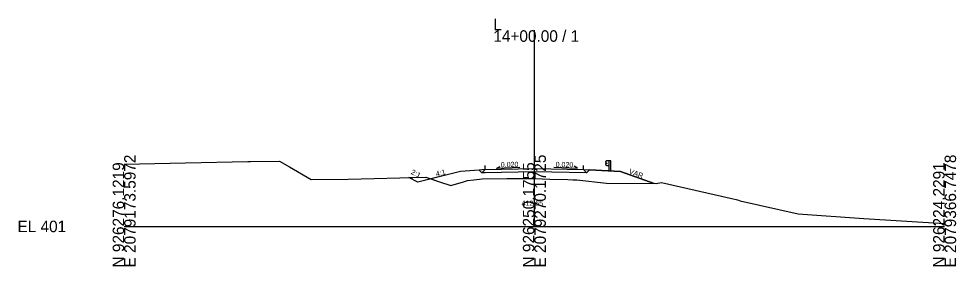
# Model space of a CAD drawing. Extents: x -26 to 10503, y -10 to 9546.
# Drawn here: x -25.7 to 202.8, y 7990.3 to 8050.5 of the extents above; entities that cross this region are included whole.
import ezdxf

# ---------------------------------------------------------------- set-up
doc = ezdxf.new("R2010")
doc.units = 0
for name, color, linetype in [('Default', 7, 'Continuous'), ('Exist XS Center Line Elevation Label', 7, 'Continuous'), ('Exist XS Ground Line', 7, 'Continuous'), ('Old_Level_3', 7, 'Continuous'), ('Old_Level_58', 7, 'Continuous'), ('Old_Level_63', 7, 'Continuous'), ('Old_Level_8', 7, 'Continuous'), ('Prop XS Ditch Slope Text', 7, 'Continuous'), ('Prop XS EOT Tick Mark', 7, 'Continuous'), ('Prop XS Finish Grade', 7, 'Continuous'), ('Prop XS Finish Grade Earthwork', 7, 'Continuous'), ('Prop XS Finish Grade Pavement', 7, 'Continuous'), ('Prop XS Pvmt Edge Slope', 7, 'Continuous'), ('Prop XS SE Text', 7, 'Continuous'), ('Prop XS Side Slope Text', 7, 'Continuous'), ('Prop XS Subgrade Earthwork', 7, 'Continuous')]:
    doc.layers.add(name, color=color, linetype=linetype)

msp = doc.modelspace()

# ---------------------------------------------------------------- linework, layer by layer
at = {"layer": 'Default'}
for points in [[(100, 8013.32), (88, 8013.08), (87.23, 8013.07), (86.58, 8013.72), (81.99, 8013.35), (74.8, 8011.55), (76.87, 8010.82), (79.61, 8009.92), (82.69, 8010.82), (83.66, 8011.16), (85.22, 8011.36), (87.25, 8011.62), (93.27, 8011.68), (98.23, 8011.7), (100, 8011.65), (103.79, 8011.54), (108.18, 8011.39), (109.4, 8011.34), (110.32, 8011.3), (117.57, 8010.5), (129.18, 8010.41), (121, 8013.38), (113.43, 8013.76), (112.74, 8013.07)], [(69.38, 8011.88), (73.58, 8011.99), (74.8, 8011.55), (71.63, 8010.76)]]:
    msp.add_lwpolyline(points, close=True, dxfattribs=at)
at = {"layer": 'Exist XS Ground Line'}
for p, q in [((0, 8015.12), (14.95, 8015.48)), ((14.95, 8015.48), (30.18, 8015.79)), ((30.18, 8015.79), (30.81, 8015.82)), ((30.81, 8015.82), (37.91, 8015.92)), ((37.91, 8015.92), (40.31, 8014.54)), ((40.31, 8014.54), (45.6, 8011.43)), ((45.6, 8011.43), (54.62, 8011.52)), ((54.62, 8011.52), (73.58, 8011.99)), ((73.58, 8011.99), (76.87, 8010.82)), ((76.87, 8010.82), (79.61, 8009.92)), ((79.61, 8009.92), (82.69, 8010.82)), ((82.69, 8010.82), (83.66, 8011.16)), ((83.66, 8011.16), (85.22, 8011.36)), ((85.22, 8011.36), (87.25, 8011.62)), ((87.25, 8011.62), (93.27, 8011.68)), ((93.27, 8011.68), (98.23, 8011.7)), ((98.23, 8011.7), (100, 8011.65)), ((100, 8011.65), (103.79, 8011.54)), ((103.79, 8011.54), (108.18, 8011.39)), ((108.18, 8011.39), (109.4, 8011.34)), ((109.4, 8011.34), (110.32, 8011.3)), ((110.32, 8011.3), (117.57, 8010.5)), ((117.57, 8010.5), (129.66, 8010.41)), ((129.66, 8010.41), (131, 8010.67)), ((131, 8010.67), (148.44, 8006.75)), ((148.44, 8006.75), (149.16, 8006.52)), ((149.16, 8006.52), (149.76, 8006.35)), ((149.76, 8006.35), (150.18, 8006.25)), ((150.18, 8006.25), (164.34, 8003.08)), ((164.34, 8003.08), (180.34, 8001.89)), ((180.34, 8001.89), (200, 8000.69))]:
    msp.add_line(p, q, dxfattribs=at)
at = {"layer": 'Old_Level_3'}
for p, q in [((117.35, 8015.73), (117.32, 8015.67)), ((117.32, 8015.67), (117.35, 8015.61)), ((117.35, 8015.11), (117.32, 8015.05)), ((117.32, 8015.05), (117.35, 8014.99)), ((117.64, 8015.93), (117.35, 8015.73)), ((117.35, 8015.61), (117.64, 8015.41)), ((117.64, 8015.31), (117.35, 8015.11)), ((117.35, 8014.99), (117.64, 8014.79)), ((118.14, 8015.93), (117.64, 8015.93)), ((117.64, 8015.41), (117.64, 8015.31)), ((117.64, 8014.79), (118.14, 8014.79)), ((118.64, 8015.93), (118.14, 8015.93)), ((118.14, 8015.93), (118.14, 8013.53)), ((118.64, 8013.5), (118.64, 8015.93))]:
    msp.add_line(p, q, dxfattribs=at)
at = {"layer": 'Old_Level_63'}
for p, q in [((100, 8000), (100, 8047.75)), ((0, 8000), (100, 8000)), ((100, 8000), (200, 8000))]:
    msp.add_line(p, q, dxfattribs=at)
at = {"layer": 'Old_Level_8'}
msp.add_line((112, 8013.83), (112.74, 8013.07), dxfattribs=at)
at = {"layer": 'Prop XS EOT Tick Mark'}
for p, q in [((88, 8013.83), (88, 8014.83)), ((112, 8013.83), (112, 8014.83))]:
    msp.add_line(p, q, dxfattribs=at)
at = {"layer": 'Prop XS Finish Grade'}
for p, q in [((88, 8013.83), (86.58, 8013.72)), ((112, 8013.83), (113.43, 8013.76))]:
    msp.add_line(p, q, dxfattribs=at)
at = {"layer": 'Prop XS Finish Grade Earthwork'}
for p, q in [((81.99, 8013.35), (71.63, 8010.76)), ((86.58, 8013.72), (81.99, 8013.35)), ((113.43, 8013.76), (121, 8013.38)), ((121, 8013.38), (129.18, 8010.41)), ((71.63, 8010.76), (69.38, 8011.88))]:
    msp.add_line(p, q, dxfattribs=at)
at = {"layer": 'Prop XS Finish Grade Pavement'}
for p, q in [((88, 8013.83), (100, 8014.07)), ((100, 8014.07), (112, 8013.83))]:
    msp.add_line(p, q, dxfattribs=at)
at = {"layer": 'Prop XS Pvmt Edge Slope'}
msp.add_line((88, 8013.83), (87.23, 8013.07), dxfattribs=at)
at = {"layer": 'Prop XS SE Text'}
for points in [[(104.77, 8014.46), (110.52, 8014.18), (109.67, 8014.65)], [(96.49, 8014.38), (90.73, 8014.1), (91.58, 8014.57)]]:
    msp.add_lwpolyline(points, dxfattribs=at)
at = {"layer": 'Prop XS Subgrade Earthwork'}
for p, q in [((87.23, 8013.07), (86.58, 8013.72)), ((88, 8013.08), (87.23, 8013.07)), ((100, 8013.32), (88, 8013.08)), ((112.74, 8013.07), (100, 8013.32)), ((112.74, 8013.07), (113.43, 8013.76))]:
    msp.add_line(p, q, dxfattribs=at)

# ---------------------------------------------------------------- texts
at = {"layer": 'Exist XS Center Line Elevation Label'}
msp.add_text('412.65', height=1.25, rotation=360, dxfattribs=at).set_placement((96.86, 8005.02))
at = {"layer": 'Old_Level_58'}
msp.add_text('Case1', height=0.04, dxfattribs=at).set_placement((118.14, 8013.43))
at = {"layer": 'Old_Level_63'}
for s, p in [('L', (90, 8047.75)), ('14+00.00 / 1', (90, 8044.95)), ('EL 401', (-26, 7998.6))]:
    msp.add_text(s, height=2.8, dxfattribs=at).set_placement(p)
for s, p in [('E 2079173.5972', (2.8, 7990)), ('E 2079270.1725', (102.8, 7990)), ('E 2079366.7478', (202.8, 7990)), ('N 926276.1219', (0, 7990)), ('N 926250.1755', (100, 7990)), ('N 926224.2291', (200, 7990))]:
    msp.add_text(s, height=2.8, rotation=90, dxfattribs=at).set_placement(p)
at = {"layer": 'Prop XS Ditch Slope Text'}
msp.add_text('4:1', height=1.25, rotation=14.0362, dxfattribs=at).set_placement((76.13, 8012.14))
at = {"layer": 'Prop XS SE Text'}
for rotation, p in [(1.1458, (91.81, 8014.41)), (358.8542, (105.16, 8014.47))]:
    msp.add_text('0.020', height=1.25, rotation=rotation, dxfattribs=at).set_placement(p)
at = {"layer": 'Prop XS Side Slope Text'}
for s, rotation, p in [('2:1', 333.4349, (69.79, 8012.83)), ('VAR', 339.556, (122.94, 8012.91))]:
    msp.add_text(s, height=1.25, rotation=rotation, dxfattribs=at).set_placement(p)

doc.saveas('drawing.dxf')
